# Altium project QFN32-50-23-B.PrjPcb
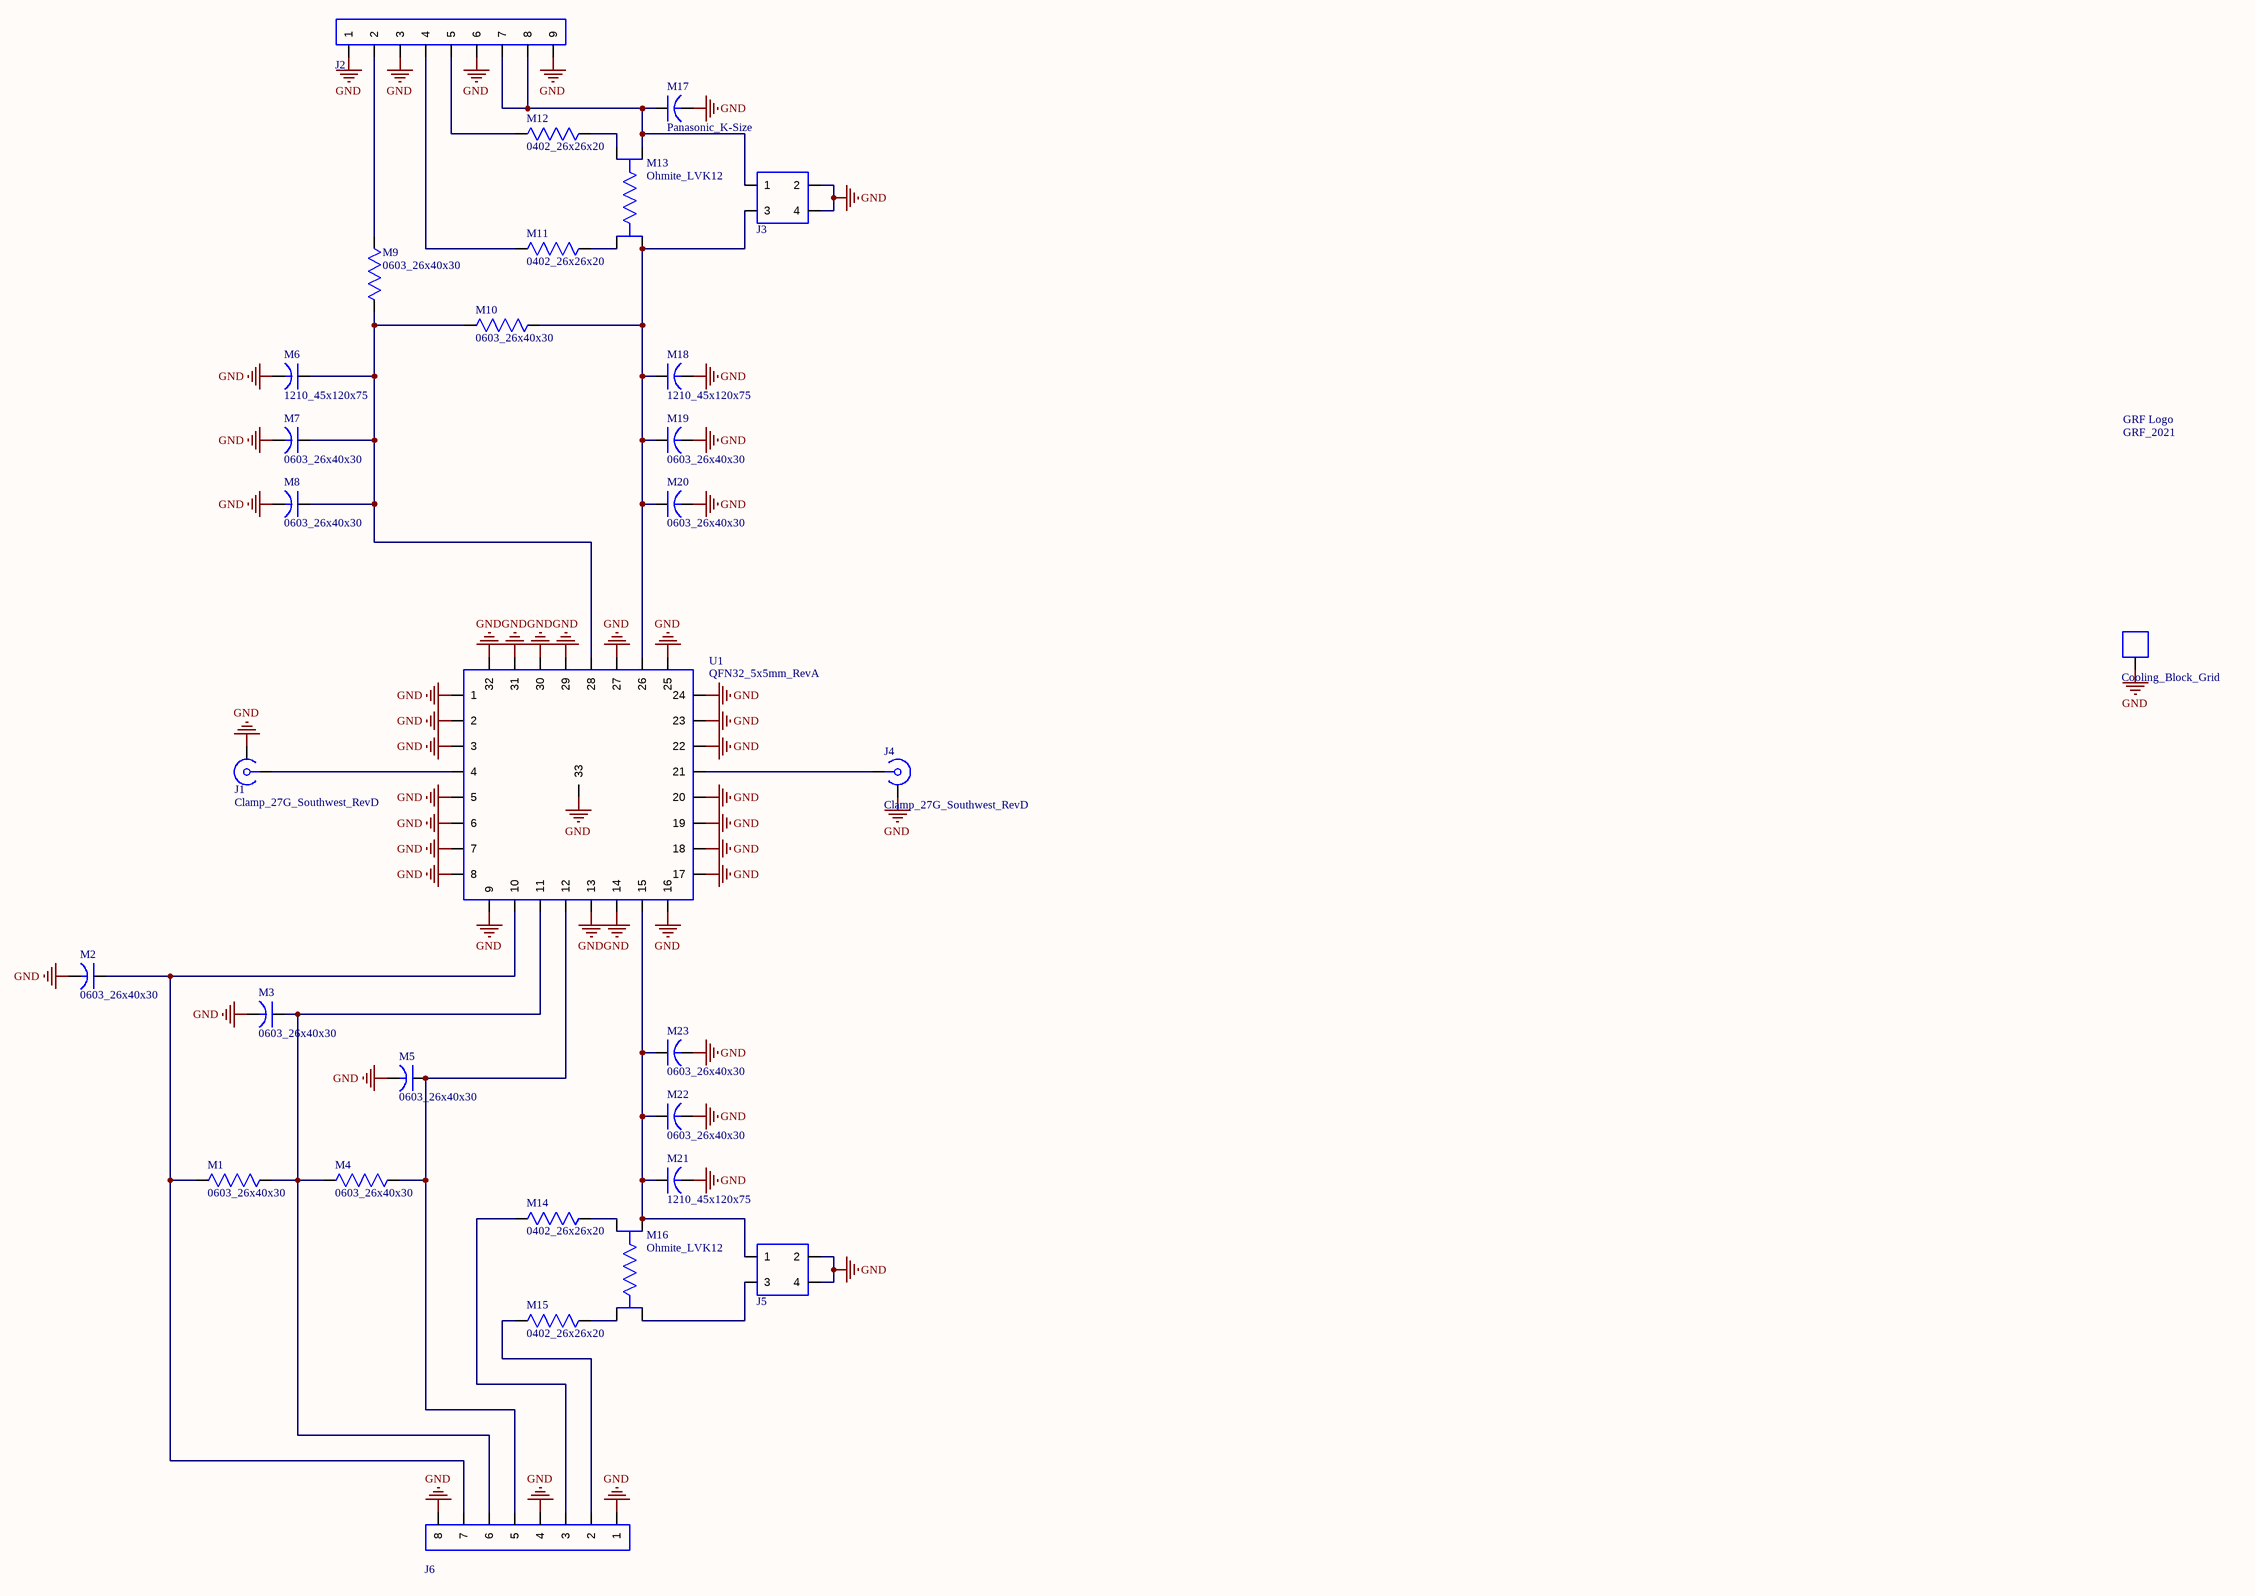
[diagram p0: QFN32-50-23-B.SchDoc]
Description: Layout updates; Modified From: DFN6-15-34-A (Eagle)
1 sheet, 32 parts. Net scope: global (net labels, ports and power ports of the same name join across sheets).
Board file: QFN32-50-23-B.PcbDoc

## Sheet QFN32-50-23-B.SchDoc
size 609 x 419 mm; Revision: A; SheetNumber: 1; SheetTotal: 1

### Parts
H1  Cooling_Block_Grid  [Cooling_Block_Grid]
J1  Clamp_27G_Southwest_RevD  [Clamp_27G_Southwest_RevD]
J2  Header_H_9-Pin_100mil  [Header_H_9-Pin_100mil]  (value not drawn)
J3  Header_SMD_Dual-2-Pin_100Mil  [Header_SMD_Dual-2-Pin_100Mil]  (value not drawn)
J4  Clamp_27G_Southwest_RevD  [Clamp_27G_Southwest_RevD]
J5  Header_SMD_Dual-2-Pin_100Mil  [Header_SMD_Dual-2-Pin_100Mil]  (value not drawn)
J6  Header_H_8-Pin_100mil  [Header_H_8-Pin_100mil]  (value not drawn)
Logo1  GRF_2021  [GRF_2021]
M1  0603_26x40x30  [0603_26x40x30]
M2  0603_26x40x30  [0603_26x40x30]
M3  0603_26x40x30  [0603_26x40x30]
M4  0603_26x40x30  [0603_26x40x30]
M5  0603_26x40x30  [0603_26x40x30]
M6  1210_45x120x75  [1210_45x120x75]
M7  0603_26x40x30  [0603_26x40x30]
M8  0603_26x40x30  [0603_26x40x30]
M9  0603_26x40x30  [0603_26x40x30]
M10  0603_26x40x30  [0603_26x40x30]
M11  0402_26x26x20  [0402_26x26x20]
M12  0402_26x26x20  [0402_26x26x20]
M13  Ohmite_LVK12  [Ohmite_LVK12]
M14  0402_26x26x20  [0402_26x26x20]
M15  0402_26x26x20  [0402_26x26x20]
M16  Ohmite_LVK12  [Ohmite_LVK12]
M17  Panasonic_K-Size  [Panasonic_K-Size]
M18  1210_45x120x75  [1210_45x120x75]
M19  0603_26x40x30  [0603_26x40x30]
M20  0603_26x40x30  [0603_26x40x30]
M21  1210_45x120x75  [1210_45x120x75]
M22  0603_26x40x30  [0603_26x40x30]
M23  0603_26x40x30  [0603_26x40x30]
U1  QFN32_5x5mm_RevA  [QFN32_5x5mm_RevA]

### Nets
GND: H1.1 J1.2 J2.1 J2.3 J2.6 J2.9 J3.2 J3.4 J4.2 J5.2 J5.4 J6.1 J6.4 J6.8 M2.1 M3.1 M5.1 M6.1 M7.1 M8.1 M17.1 M18.1 M19.1 M20.1 M21.1 M22.1 M23.1 U1.1 U1.2 U1.3 U1.5 U1.6 U1.7 U1.8 U1.9 U1.13 U1.14 U1.16 U1.17 U1.18 U1.19 U1.20 U1.22 U1.23 U1.24 U1.25 U1.27 U1.29 U1.30 U1.31 U1.32 U1.33
NetJ1_1: J1.1 U1.4
NetJ2_2: J2.2 M9.2
NetJ2_4: J2.4 M11.1
NetJ2_5: J2.5 M12.1
NetJ2_7: J2.7 J2.8 J3.1 M13.2 M17.2
NetJ3_3: J3.3 M10.2 M13.1 M18.2 M19.2 M20.2 U1.26
NetJ4_1: J4.1 U1.21
NetJ5_1: J5.1 M16.2 M21.2 M22.2 M23.2 U1.15
NetJ5_3: J5.3 M16.1
NetJ6_2: J6.2 M15.1
NetJ6_3: J6.3 M14.1
NetJ6_5: J6.5 M4.1 M5.2 U1.12
NetJ6_6: J6.6 M1.1 M3.2 M4.2 U1.11
NetJ6_7: J6.7 M1.2 M2.2 U1.10
NetM6_2: M6.2 M7.2 M8.2 M9.1 M10.1 U1.28
NetM11_2: M11.2 M13.4
NetM12_2: M12.2 M13.3
NetM14_2: M14.2 M16.3
NetM15_2: M15.2 M16.4

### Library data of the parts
H1 = Mounting Holes
J1 J4 = RF_Conn
J2 = Header_9-Pin: Header 9-Pin
J3 J5 = Header_Dual-2-Pin: Header 4-Pin
J6 = Header_8-Pin: Header 8-Pin
Logo1 = GRF_Logo: =CurrentFootprint
M1 M4 M9-M12 M14 M15 = Resistor
M2 M3 M5-M8 M18-M23 = Capacitor
M13 M16 = Resistor_Ohmite_Current_Sense
M17 = Capacitor_Panasonic_K
U1 = QFN32_5x5mm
